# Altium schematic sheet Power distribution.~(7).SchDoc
size A3; SheetNumber: 4; SheetTotal: 4
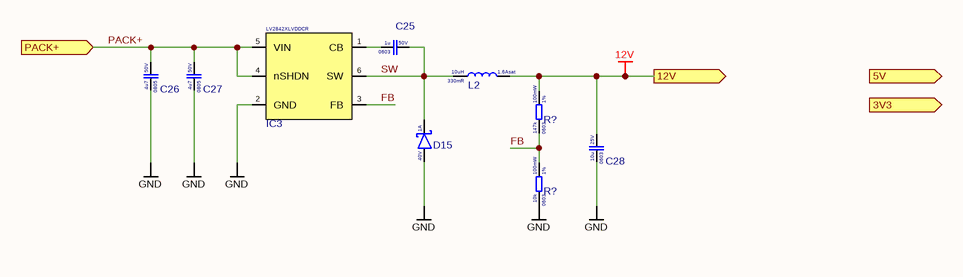
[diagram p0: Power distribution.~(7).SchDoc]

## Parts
(Parts that share a designator on the sheet are numbered #1, #2 ... from top to bottom, then left to right.)
C25  Voltage Rating: 50V  Case Code (Imperial): 0603  Capacitance: 1u  [CAP 0603]  (hidden comment: CL10A105KB8NNNC)
C26  Voltage Rating: 50V  Case Code (Imperial): 0805  Capacitance: 4u7  [Cap_0805]  (hidden comment: CL21A475KBQNNNE)
C27  Voltage Rating: 50V  Case Code (Imperial): 0805  Capacitance: 4u7  [Cap_0805]  (hidden comment: CL21A475KBQNNNE)
C28  Voltage Rating: 25V  Case Code (Imperial): 0603  Capacitance: 10u  [CAP 0603]  (hidden comment: CL10A106MA8NRNC)
D15  Forward Current: 1A  Reverse Voltage: 40V  [SOD-323]  (hidden comment: 1N5819WS)
IC3  LV2842XLVDDCR  [SOT-23-6]
L2  Resistance: 330mR  Saturation current: 1.6Asat  Inductance: 10uH  [IND 1008]  (hidden comment: FTC252012S100MBCA)
R?#1  Resistance Tolerance: 1%  Resistance: 147k  Power Rating: 100mW  Case Code (Imperial): 0603  [RES_0603]  (hidden comment: 0603WAF1473T5E)
R?#2  Resistance Tolerance: 1%  Resistance: 10k  Power Rating: 100mW  Case Code (Imperial): 0603  [RES_0603]  (hidden comment: 0603WAF1002T5E)

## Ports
3V3 (out, see Arhitecture[5C]), 5V (out, see Arhitecture[5C]), 12V (out, see Arhitecture[5C], Charger[1A]), PACK+ (in, see Arhitecture[6C], Battery level indicator[3B], Charger[8A])

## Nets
12V: C28.2 L2.2 R?#1.2 ; port 12V
GND: C26.1 C27.1 C28.1 D15.A IC3.2(GND) R?#2.1
FB: IC3.3(FB) R?#1.1 R?#2.2
PACK+: C26.2 C27.2 IC3.4(nSHDN) IC3.5(VIN) ; port PACK+
SW: C25.2 D15.K IC3.6(SW) L2.1
NetC25_1: C25.1 IC3.1(CB)

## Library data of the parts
C25 = CL10A105KB8NNNC: Cap 1uF 50V 0603 X5R; Manufacturer: Samsung
C26 C27 = CL21A475KBQNNNE: Cap 4.7uF 50V 0805 X5R; Manufacturer: Samsung
C28 = CL10A106MA8NRNC: Cap 10uF 25V 0603 X5R; Manufacturer: Samsung
D15 = 1N5819WS: Schottky 40V 1A 600mVf SOD-323; Manufacturer: Guangdong Hottech
IC3 = LV2842XLVDDCR: Step-down converter 4~40Vin 600mAout Adjustible SOT23-6; Manufacturer: Texas Instruments
L2 = FTC252012S100MBCA: Inductor 10uH 1.6Asat 330mR; Manufacturer: cjiang
R?#1 = 0603WAF1473T5E: Res 147k 0603 1% 100mW 75V; Manufacturer: Uni-Royal
R?#2 = 0603WAF1002T5E: Res 10k 0603 1% 100mW 75V; Manufacturer: Uni-Royal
